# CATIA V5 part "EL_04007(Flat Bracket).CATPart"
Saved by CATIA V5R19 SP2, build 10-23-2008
Part number: EL_04007 (Chape tdb haut)
Material "Acier": density 7860 kg/m3, Young's modulus 2e+11 Pa, Poisson ratio 0.266, thermal expansion 1.17e-05 1/K
Bounding box of the stored display mesh (mm): x -5.95 to 1.5, y -10 to 0, z -27 to -7.993
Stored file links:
  C:\Users\thoma\Desktop\EPSA\ELIZ-2021\EL_Electrical\EL_A0100 (Dash Panel)\EL_04007(Flat Bracket).CATPart
  C:\Program Files (x86)\Dassault Systemes\B19\intel_a\startup\materials\French\Catalog.CATMaterial
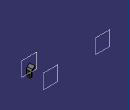
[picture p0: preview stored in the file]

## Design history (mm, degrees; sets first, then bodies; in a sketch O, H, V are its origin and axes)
SheetMetalParameters1: Thickness 1.5, BendRadius 4, KFactor 0.43175 {= log(min(100,max(20*SheetMetalParameters1.BendRadius,SheetMetalParameters1.Thickness)/SheetMetalParameters1.Thickness))/log(100)/2}, ReliefRadialLength 1, ReliefAxialLength 2, MinimumBendRadius 0
Body1 (main body), material "Acier"
  DatumCurve1
  Sketch1 on yz-plane, origin (0, 0, 0), H (0, 1, 0), V (0, 0, 1)
    line L1 (-10, -16) -> (-10, -22)
    arc A1 centre (-5, -22) radius 5 from (-10, -22) to (0, -22) ccw
    point P4 (-5, -22)
    circle A2 centre (-5, -22) radius 1.6
    reference projected circle E1 centre (-5, -22) radius 1.6 from edge of DatumCurve1
    line L2 (0, -22) -> (0, -16)
    line L3 (0, -16) -> (-10, -16)
    radius A2 = 1.6
    length L1 = 6
    length L3 = 10
    vertical: L1 V
    tangency: A1 L1, L2 A1
    concentricity: P4 E1
    horizontal: L3 H
    parallelism: L2 L1
  DatumCurve2
  Plane1: type Normal, Curve DatumCurve2
  DatumSurface1
  DatumSurface2
  Wall1: Thickness 1.5, Profile Sketch1
  DatumCurve3
  Plane2: type Normal, Curve DatumCurve3
  Plane3: type Offset, RefPlane Plane2, Offset 42
  Flange1: Guide edge [face of Wall1 | face of Wall1], Angle 130, KFacteur 0.43175 {= log(min(100,max(20*Flange1.Radius,SheetMetalParameters1.Thickness)/SheetMetalParameters1.Thickness))/log(100)/2}, Length 10, Radius 4
  DatumSurface3
  DatumSurface4
  Sketch2 on Plane3, origin (0, 37.8201, 0), H (-1, 0, 0), V (0, 0, 1)
    circle A1 centre (17.6005, 0.305) radius 15
    reference intersected arc E1 centre (17.6005, 0.305) radius 15 from (30.8984, 7.2452) to (4.3026, -6.6352) ccw from face of DatumSurface4
    radius A1 = 15
    concentricity: E1 A1
  CutOut1: Direction Sketch2, EndLimit through (limit type 2), Orientation true, Profile Sketch2, StartLimit through (limit type 2)
  DatumSurface5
